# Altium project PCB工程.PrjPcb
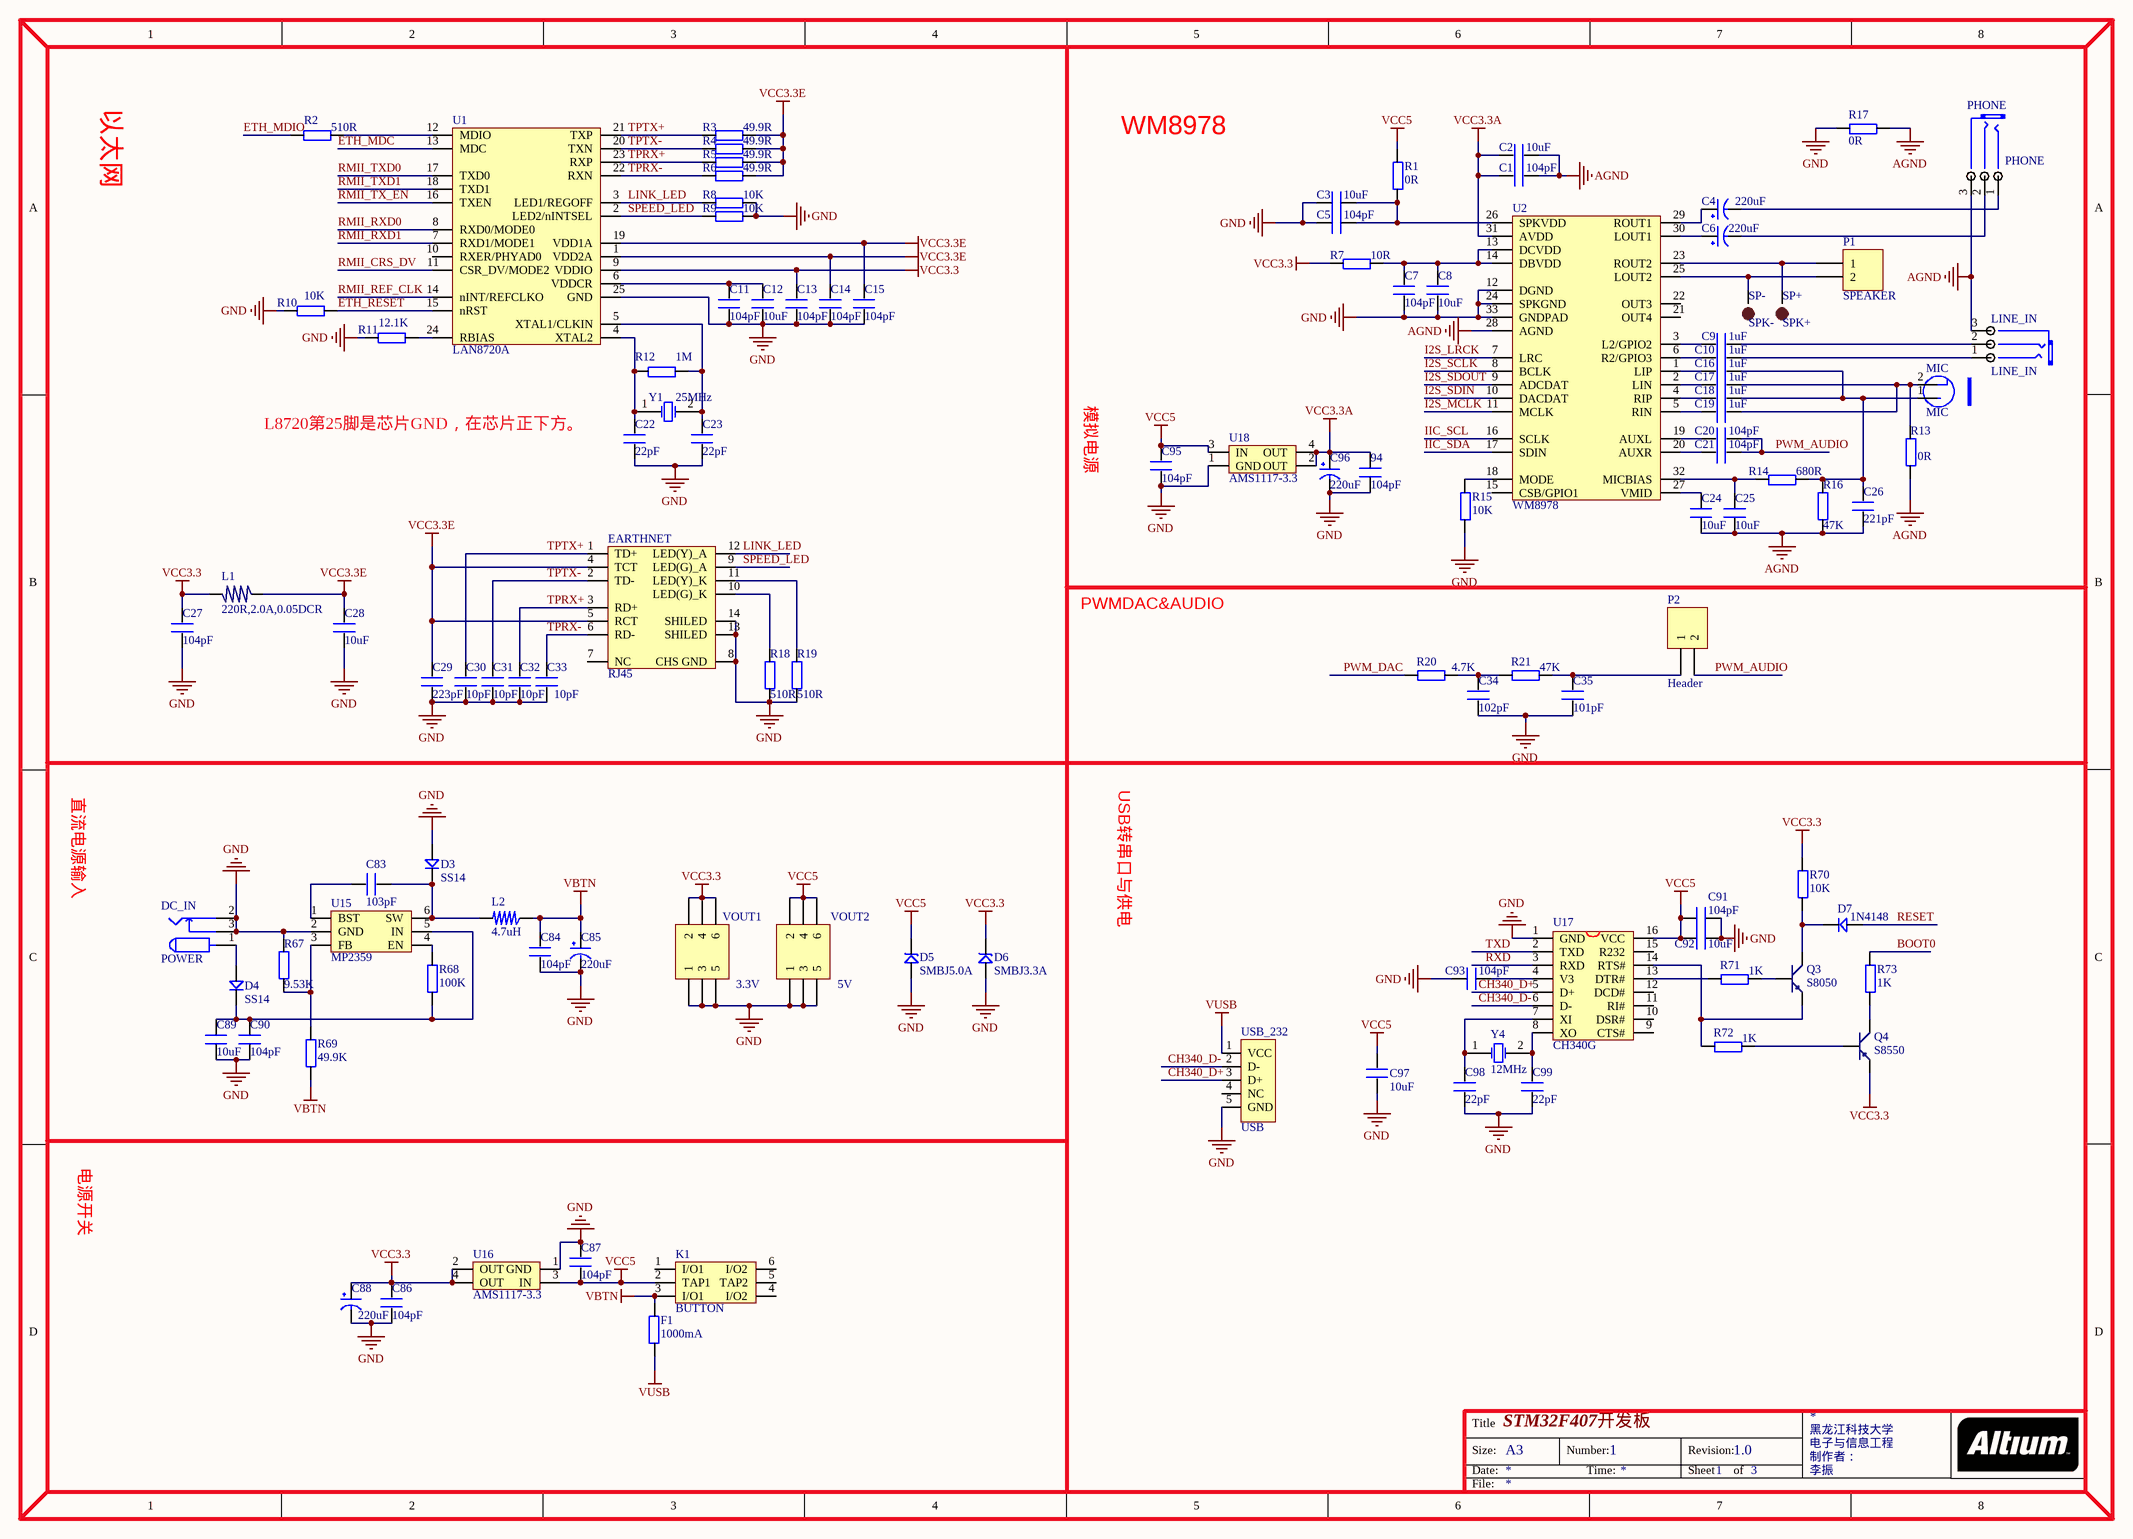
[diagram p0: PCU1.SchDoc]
3 sheets, 252 parts. Net scope: global (net labels, ports and power ports of the same name join across sheets).
Board file: PCB.PcbDoc
Sheets:
  PCU1.SchDoc
  CPU2.SchDoc
  CPU3.SchDoc

## Sheet PCU1.SchDoc: STM32F407开发板
size A3; DrawnBy: 李振; Address1: 黑龙江科技大学; Address2: 电子与信息工程; Address3: 制作者：; Address4: 李振; DocumentNumber: 1; Revision: 1.0; SheetNumber: 1; SheetTotal: 3

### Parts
94  104pF  [0603P]
C1  104pF  [0603P]
C2  10uF  [0603P]
C3  10uF  [0603P]
C4  220uF  [CC6.56.5]
C5  104pF  [0603P]
C6  220uF  [CC6.56.5]
C7  104pF  [0603P]
C8  10uF  [0603P]
C9  1uF  [0603P]
C10  1uF  [0603P]
C11  104pF  [0603P]
C12  10uF  [0603P]
C13  104pF  [0603P]
C14  104pF  [0603P]
C15  104pF  [0603P]
C16  1uF  [0603P]
C17  1uF  [0603P]
C18  1uF  [0603P]
C19  1uF  [0603P]
C20  104pF  [0603P]
C21  104pF  [0603P]
C22  22pF  [0603P]
C23  22pF  [0603P]
C24  10uF  [0603P]
C25  10uF  [0603P]
C26  221pF  [0603P]
C27  104pF  [0603P]
C28  10uF  [0603P]
C29  223pF  [0603P]
C30  10pF  [0603P]
C31  10pF  [0603P]
C32  10pF  [0603P]
C33  10pF  [0603P]
C34  102pF  [0603P]
C35  101pF  [0603P]
C83  103pF  [0603P]
C84  104pF  [0603P]
C85  220uF  [CC6.56.5]
C86  104pF  [0603P]
C87  104pF  [0603P]
C88  220uF  [CC6.56.5]
C89  10uF  [0603P]
C90  104pF  [0603P]
C91  104pF  [0603P]
C92  10uF  [0603P]
C93  104pF  [0603P]
C95  104pF  [0603P]
C96  220uF  [CC6.56.5]
C97  10uF  [0603P]
C98  22pF  [0603P]
C99  22pF  [0603P]
D3  SS14  [DIODE_SOP]
D4  SS14  [DIODE_SOP]
D5  SMBJ5.0A  [SMBJ]
D6  SMBJ3.3A  [SMBJ]
D7  1N4148  [DIODE_SOP]
DC_IN  POWER  [DC10B]
EARTHNET  RJ45  [HR911105A]
F1  1000mA  [0805]
K1  BUTTON  [BTN8.5*8.5]
L1  220R,2.0A,0.05DCR  [0603P]
L2  4.7uH  [L_SOP74]
LINE_IN  LINE_IN  [PHONE_ST]
MIC  MIC  [MIC]
P1  SPEAKER  [HDR1X2]
P2  Header  [HDR1X2]
PHONE  PHONE  [PHONE_ST]
Q3  S8050  [SOT-23R]
Q4  S8550  [SOT-23R]
R1  0R  [0603P]
R2  510R  [0603P]
R3  49.9R  [0603P]
R4  49.9R  [0603P]
R5  49.9R  [0603P]
R6  49.9R  [0603P]
R7  10R  [0603P]
R8  10K  [0603P]
R9  10K  [0603P]
R10  10K  [0603P]
R11  12.1K  [0603P]
R12  1M  [0603P]
R13  0R  [0603P]
R14  680R  [0603P]
R15  10K  [0603P]
R16  47K  [0603P]
R17  0R  [0603P]
R18  510R  [0603P]
R19  510R  [0603P]
R20  4.7K  [0603P]
R21  47K  [0603P]
R67  9.53K  [0603P]
R68  100K  [0603P]
R69  49.9K  [0603P]
R70  10K  [0603P]
R71  1K  [0603P]
R72  1K  [0603P]
R73  1K  [0603P]
SP+  SPK+  [TP-1.5]
SP-  SPK-  [TP-1.5]
U1  LAN8720A  [QFN24]
U2  WM8978  [qfn32]
U15  MP2359  [SOT-23-6]
U16  AMS1117-3.3  [AMS1117]
U17  CH340G  [SOP16M]
U18  AMS1117-3.3  [AMS1117]
USB_232  USB  [USB/SM0.8-6H5]
VOUT1  3.3V  [HDR2X3]
VOUT2  5V  [HDR2X3]
Y1  25MHz  [XTAL_US]
Y4  12MHz  [XTAL_US]

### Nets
AGND: C1.1 C2.1 C24.1 C25.1 C26.1 LINE_IN.3(COM) PHONE.3(COM) R13.1 R16.1 R17.2 U2.28(AGND)
GND: 94.1 C3.1 C5.1 C7.1 C8.1 C11.1 C12.1 C13.1 C14.1 C15.1 C22.1 C23.1 C27.1 C28.1 C29.1 C30.1 C31.1 C32.1 C33.1 C34.1 C35.1 C84.1 C85.2(GND) C86.1 C87.2 C88.2(GND) C89.1 C90.1 C91.1 C92.1 C93.1 C95.1 C96.2(GND) C97.1 C98.1 C99.1 D3.1 D5.1 D6.1 DC_IN.2 DC_IN.3 EARTHNET.8(CHS_GND) EARTHNET.13(SHILED) EARTHNET.14(SHILED) R8.2 R9.2 R10.1 R11.1 R15.1 R17.1 R18.1 R19.1 R67.2 U1.25(GND) U2.12(DGND) U2.24(SPKGND) U2.33(GNDPAD) U15.2(GND) U16.1(GND) U17.1(GND) U18.1(GND) USB_232.5(GND) VOUT1.1 VOUT1.3 VOUT1.5 VOUT2.1 VOUT2.3 VOUT2.5
VBTN: C84.2 C85.1(VCC) F1.1 K1.3(I/O1) L2.1 R69.1
VCC3.3: C13.2 C27.2 C86.2 C88.1(VCC) D6.2 L1.2 Q4.1(E) R7.1 R70.2 U1.9(VDDIO) U16.2(OUT) U16.4(OUT) VOUT1.2 VOUT1.4 VOUT1.6
VCC3.3A: 94.2 C1.2 C2.2 C96.1(VCC) U2.31(AVDD) U18.2(OUT) U18.4(OUT)
VCC3.3E: C14.2 C15.2 C28.2 C29.2 EARTHNET.4(TCT) EARTHNET.5(RCT) L1.1 R3.2 R4.2 R5.2 R6.2 U1.1(VDD2A) U1.19(VDD1A)
VCC5: C87.1 C91.2 C92.2 C95.2 C97.2 D5.2 K1.2(TAP1) R1.2 U16.3(IN) U17.16(VCC) U18.3(IN) VOUT2.2 VOUT2.4 VOUT2.6
VUSB: F1.2 USB_232.1(VCC)
BOOT0: R73.2
CH340_D+: U17.5(D+) USB_232.3(D+)
CH340_D-: U17.6(D-) USB_232.2(D-)
ETH_MDC: U1.13(MDC)
ETH_MDIO: R2.1
ETH_RESET: R10.2 U1.15(nRST)
I2S_LRCK: U2.7(LRC)
I2S_MCLK: U2.11(MCLK)  [project net DCMI_D0]
I2S_SCLK: U2.8(BCLK)
I2S_SDIN: U2.10(DACDAT)
I2S_SDOUT: U2.9(ADCDAT)
IIC_SCL: U2.16(SCLK)
IIC_SDA: U2.17(SDIN)
LINK_LED: EARTHNET.12(LED(Y)_A) R8.1 U1.3(LED1/REGOFF)
PWM_AUDIO: C20.2 C21.2 P2.2
PWM_DAC: R20.1  [project net PA3]
RESET: D7.1
RMII_CRS_DV: U1.11(CSR_DV/MODE2)  [project net PA7]
RMII_REF_CLK: U1.14(nINT/REFCLKO)  [project net PA1]
RMII_RXD0: U1.8(RXD0/MODE0)  [project net PC4]
RMII_RXD1: U1.7(RXD1/MODE1)  [project net PC5]
RMII_TX_EN: U1.16(TXEN)  [project net PG11]
RMII_TXD0: U1.17(TXD0)  [project net PG13]
RMII_TXD1: U1.18(TXD1)  [project net PG14]
RXD: U17.3(RXD)
SPEED_LED: EARTHNET.9(LED(G)_A) R9.1 U1.2(LED2/nINTSEL)
TPRX+: C32.2 EARTHNET.3(RD+) R5.1 U1.23(RXP)
TPRX-: C33.2 EARTHNET.6(RD-) R6.1 U1.22(RXN)
TPTX+: C30.2 EARTHNET.1(TD+) R3.1 U1.21(TXP)
TPTX-: C31.2 EARTHNET.2(TD-) R4.1 U1.20(TXN)
TXD: U17.2(TXD)
NetC3_2: C3.2 C5.2 R1.1 U2.26(SPKVDD)
NetC4_1: C4.1(VCC) U2.29(ROUT1)
NetC4_2: C4.2(GND) PHONE.1(CHL)
NetC6_1: C6.1(VCC) U2.30(LOUT1)
NetC6_2: C6.2(GND) PHONE.2(CHR)
NetC7_2: C7.2 C8.2 R7.2 U2.13(DCVDD) U2.14(DBVDD)
NetC9_1: C9.1 U2.3(L2/GPIO2)
NetC9_2: C9.2 LINE_IN.2(CHR)
NetC10_1: C10.1 U2.6(R2/GPIO3)
NetC10_2: C10.2 LINE_IN.1(CHL)
NetC11_2: C11.2 C12.2 U1.6(VDDCR)
NetC16_1: C16.1 U2.1(LIP)
NetC16_2: C16.2 C18.2 C26.2 MIC.1(VCC) R14.2 R16.2
NetC17_1: C17.1 U2.2(LIN)
NetC17_2: C17.2 C19.2 MIC.2(GND) R13.2
NetC18_1: C18.1 U2.4(RIP)
NetC19_1: C19.1 U2.5(RIN)
NetC20_1: C20.1 U2.19(AUXL)
NetC21_1: C21.1 U2.20(AUXR)
NetC22_2: C22.2 R12.1 U1.4(XTAL2) Y1.1(OSC1)
NetC23_2: C23.2 R12.2 U1.5(XTAL1/CLKIN) Y1.2(OSC2)
NetC24_2: C24.2 U2.27(VMID)
NetC25_2: C25.2 R14.1 U2.32(MICBIAS)
NetC34_2: C34.2 R20.2 R21.1
NetC35_2: C35.2 P2.1 R21.2
NetC83_1: C83.1 U15.1(BST)
NetC83_2: C83.2 D3.2 L2.2 U15.6(SW)
NetC89_2: C89.2 C90.2 D4.2 R68.1 U15.5(IN)
NetC93_2: C93.2 U17.4(V3)
NetC98_2: C98.2 U17.7(XI) Y4.1(OSC1)
NetC99_2: C99.2 U17.8(XO) Y4.2(OSC2)
NetD4_1: D4.1 DC_IN.1
NetD7_2: D7.2 Q3.3(C) R70.1
NetEARTHNET_10: EARTHNET.10(LED(G)_K) R18.2
NetEARTHNET_11: EARTHNET.11(LED(Y)_K) R19.2
NetP1_1: P1.1 SP+.1 U2.23(ROUT2)
NetP1_2: P1.2 SP-.1 U2.25(LOUT2)
NetQ3_1: Q3.1(E) R72.1 U17.14(RTS#)
NetQ3_2: Q3.2(B) R71.2
NetQ4_2: Q4.2(B) R72.2
NetQ4_3: Q4.3(C) R73.1
NetR2_2: R2.2 U1.12(MDIO)
NetR11_2: R11.2 U1.24(RBIAS)
NetR15_2: R15.2 U2.18(MODE)
NetR67_1: R67.1 R69.2 U15.3(FB)
NetR68_2: R68.2 U15.4(EN)
NetR71_1: R71.1 U17.13(DTR#)

Not connected (* = marked no-connect by the designer): EARTHNET 7(NC); K1 1(I/O1) 4(I/O2) 5(TAP2) 6(I/O2); U1 10(RXER/PHYAD0); U2 15(CSB/GPIO1) 21(OUT4) 22(OUT3); U17 9(CTS#) 10(DSR#) 11(RI#) 12(DCD#) 15(R232); USB_232 4(NC)

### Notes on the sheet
- 以太网
- WM8978
- L8720第25脚是芯片GND，在芯片正下方。
- 模拟电源
- PWMDAC&AUDIO
- 直流电源输入
- USB转串口与供电
- 电源开关

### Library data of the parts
94 C1-C3 C5 C7-C35 C83 C84 C86 C87 C89-C93 C95 C97-C99 = C
C4 C6 C85 C88 C96 = CAP
D3 D4 D7 = D
D5 D6 = SMBJ: TVS
DC_IN = POW
EARTHNET = HR911105
F1 R1-R21 R67-R73 = R
L1 = L
L2 = L_SOP
LINE_IN PHONE = PHONE_M
P1 = Header 2_1: Header, 2-Pin
P2 = Header 2: Header, 2-Pin
Q3 = NPN: 8050/BCW846/BCW847
Q4 = PNP: 8550/BCW68
SP+ SP- = TEST-POINT: 测试点
U1 = LAN8720: ETH PHY
U2 = WM8978: 24bit ADC&DAC
U15 = MP2359: DC DC Step Down IC
U16 U18 = AMS1117
U17 = CH340G: USB2UART
USB_232 = USB5
VOUT1 VOUT2 = Header 3X2: Header, 3-Pin, Dual row
Y1 Y4 = XTAL: Crystal Oscillator

## Sheet CPU2.SchDoc: STM32F407开发板
size A3; DrawnBy: 李振; Address1: 黑龙江科技大学; Address2: 电子与信息工程; Address3: 制作者：; Address4: 李振; DocumentNumber: 2; Revision: 1.0; SheetNumber: 2; SheetTotal: 3
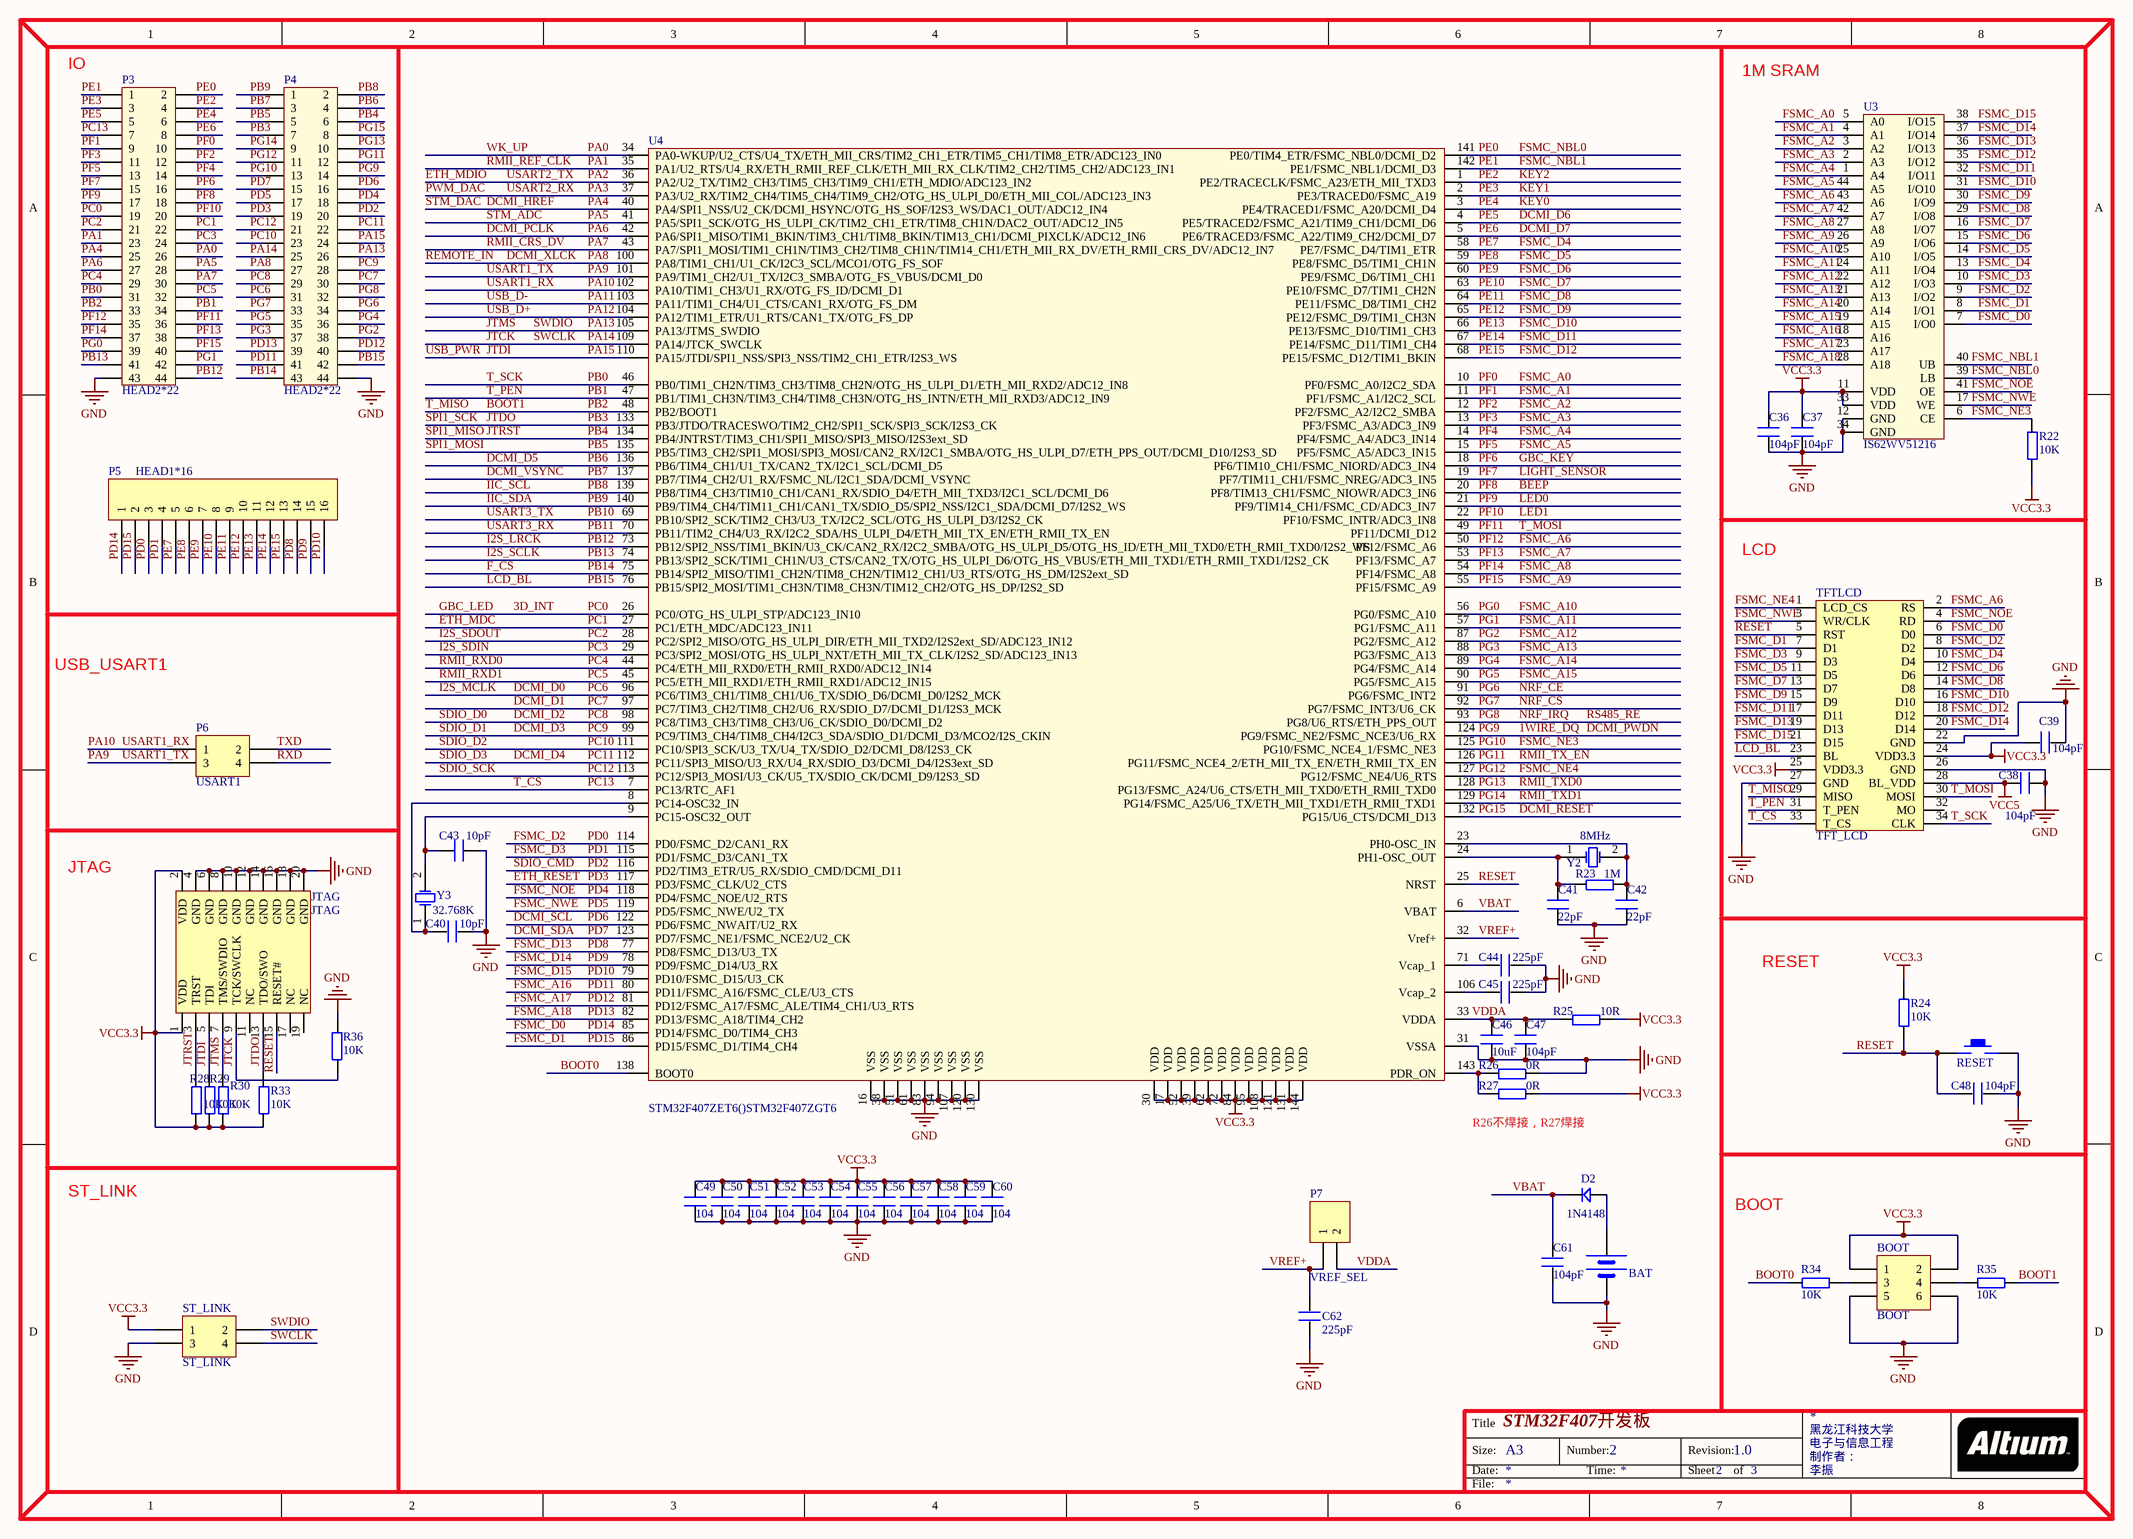
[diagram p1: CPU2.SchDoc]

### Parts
BAT  BATT  [BATM]  (value not drawn)
BOOT  BOOT  [HDR2X3]
C36  104pF  [0603P]
C37  104pF  [0603P]
C38  104pF  [0603P]
C39  104pF  [0603P]
C40  10pF  [0603P]
C41  22pF  [0603P]
C42  22pF  [0603P]
C43  10pF  [0603P]
C44  225pF  [0805]
C45  225pF  [0805]
C46  10uF  [0603P]
C47  104pF  [0603P]
C48  104pF  [0603P]
C49  104  [0603P]
C50  104  [0603P]
C51  104  [0603P]
C52  104  [0603P]
C53  104  [0603P]
C54  104  [0603P]
C55  104  [0603P]
C56  104  [0603P]
C57  104  [0603P]
C58  104  [0603P]
C59  104  [0603P]
C60  104  [0603P]
C61  104pF  [0603P]
C62  225pF  [0805]
D2  1N4148  [DIODE_SOP]
JTAG  JTAG  [JTAG_20]
P3  HEAD2*22  [HEAD2*22]
P4  HEAD2*22  [HEAD2*22]
P5  HEAD1*16  [HDR1X16]
P6  USART1  [HDR2X2]
P7  VREF_SEL  [HDR1X2]
R22  10K  [0603P]
R23  1M  [0603P]
R24  10K  [0603P]
R25  10R  [0603P]
R26  0R  [0603P]
R27  0R  [0603P]
R28  10K  [0603P]
R29  10K  [0603P]
R30  10K  [0603P]
R33  10K  [0603P]
R34  10K  [0603P]
R35  10K  [0603P]
R36  10K  [0603P]
RESET  KEY_M  [KEY_M]  (value not drawn)
ST_LINK  ST_LINK  [HDR2X2]
TFTLCD  TFT_LCD  [db2*17-4.3]
U3  IS62WV51216  [TSOP44]
U4  STM32F407ZET6()STM32F407ZGT6  [LQFP144]
Y2  8MHz  [XTAL_US]
Y3  32.768K  [XTAL32]

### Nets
GND: BAT.2(GND) BOOT.5 BOOT.6 C36.1 C37.1 C38.2 C39.2 C40.2 C41.1 C42.1 C43.2 C44.2 C45.2 C46.1 C47.1 C48.1 C49.1 C50.1 C51.1 C52.1 C53.1 C54.1 C55.1 C56.1 C57.1 C58.1 C59.1 C60.1 C61.1 C62.1 JTAG.4(GND) JTAG.6(GND) JTAG.8(GND) JTAG.10(GND) JTAG.12(GND) JTAG.14(GND) JTAG.16(GND) JTAG.18(GND) JTAG.20(GND) P3.43 P4.44 R26.2 R36.1 RESET.2 ST_LINK.3 TFTLCD.22(GND) TFTLCD.26(GND) TFTLCD.27(GND) U3.12(GND) U3.34(GND) U4.16(VSS) U4.31(VSSA) U4.38(VSS) U4.51(VSS) U4.61(VSS) U4.83(VSS) U4.94(VSS) U4.107(VSS) U4.120(VSS) U4.130(VSS)
VCC3.3: BOOT.1 BOOT.2 C36.2 C37.2 C39.1 C49.2 C50.2 C51.2 C52.2 C53.2 C54.2 C55.2 C56.2 C57.2 C58.2 C59.2 C60.2 JTAG.1(VDD) JTAG.2(VDD) R22.1 R24.2 R25.2 R27.2 R28.1 R29.1 R30.1 R33.1 ST_LINK.1 TFTLCD.24(VDD3.3) TFTLCD.25(VDD3.3) U3.11(VDD) U3.33(VDD) U4.17(VDD) U4.30(VDD) U4.39(VDD) U4.52(VDD) U4.62(VDD) U4.72(VDD) U4.84(VDD) U4.95(VDD) U4.108(VDD) U4.121(VDD) U4.131(VDD) U4.144(VDD)
VCC5: C38.1 TFTLCD.28(BL_VDD)
1WIRE_DQ: P4.14 U4.124(PG9/FSMC_NE2/FSMC_NCE3/U6_RX)  [also labelled DCMI_PWDN, PG9]
3D_INT: P3.19 U4.26(PC0/OTG_HS_ULPI_STP/ADC123_IN10)  [also labelled GBC_LED, PC0]
BEEP: P3.18 U4.20(PF8/TIM13_CH1/FSMC_NIOWR/ADC3_IN6)  [also labelled PF8]
BOOT0: R34.1 U4.138(BOOT0)
BOOT1: P3.33 R35.2 TFTLCD.29(MISO) U4.48(PB2/BOOT1)  [also labelled PB2, T_MISO]
DCMI_D0: P4.31 U4.96(PC6/TIM3_CH1/TIM8_CH1/U6_TX/SDIO_D6/DCMI_D0/I2S2_MCK)  [also labelled I2S_MCLK, PC6]
DCMI_D1: P4.30 U4.97(PC7/TIM3_CH2/TIM8_CH2/U6_RX/SDIO_D7/DCMI_D1/I2S3_MCK)  [also labelled PC7]
DCMI_D2: P4.29 U4.98(PC8/TIM3_CH3/TIM8_CH3/U6_CK/SDIO_D0/DCMI_D2)  [also labelled PC8, SDIO_D0]
DCMI_D3: P4.28 U4.99(PC9/TIM3_CH4/TIM8_CH4/I2C3_SDA/SDIO_D1/DCMI_D3/MCO2/I2S_CKIN)  [also labelled PC9, SDIO_D1]
DCMI_D4: P4.22 U4.112(PC11/SPI3_MISO/U3_RX/U4_RX/SDIO_D3/DCMI_D4/I2S3ext_SD)  [also labelled PC11, SDIO_D3]
DCMI_D5: P4.4 U4.136(PB6/TIM4_CH1/U1_TX/CAN2_TX/I2C1_SCL/DCMI_D5)  [also labelled PB6]
DCMI_D6: P3.5 U4.4(PE5/TRACED2/FSMC_A21/TIM9_CH1/DCMI_D6)  [also labelled PE5]
DCMI_D7: P3.8 U4.5(PE6/TRACED3/FSMC_A22/TIM9_CH2/DCMI_D7)  [also labelled PE6]
DCMI_HREF: P3.25 U4.40(PA4/SPI1_NSS/U2_CK/DCMI_HSYNC/OTG_HS_SOF/I2S3_WS/DAC1_OUT/ADC12_IN4)  [also labelled PA4, STM_DAC]
DCMI_PCLK: P3.27 U4.42(PA6/SPI1_MISO/TIM1_BKIN/TIM3_CH1/TIM8_BKIN/TIM13_CH1/DCMI_PIXCLK/ADC12_IN6)  [also labelled PA6]
DCMI_RESET: P4.8 U4.132(PG15/U6_CTS/DCMI_D13)  [also labelled PG15]
DCMI_SCL: P4.16 U4.122(PD6/FSMC_NWAIT/U2_RX)  [also labelled PD6]
DCMI_SDA: P4.15 U4.123(PD7/FSMC_NE1/FSMC_NCE2/U2_CK)  [also labelled PD7]
DCMI_VSYNC: P4.3 U4.137(PB7/TIM4_CH2/U1_RX/FSMC_NL/I2C1_SDA/DCMI_VSYNC)  [also labelled PB7]
DCMI_XLCK: P4.27 U4.100(PA8/TIM1_CH1/U1_CK/I2C3_SCL/MCO1/OTG_FS_SOF)  [also labelled PA8, REMOTE_IN]
ETH_MDC: P3.22 U4.27(PC1/ETH_MDC/ADC123_IN11)  [also labelled PC1]
ETH_MDIO: U4.36(PA2/U2_TX/TIM2_CH3/TIM5_CH3/TIM9_CH1/ETH_MDIO/ADC123_IN2)  [also labelled PA2, USART2_TX]
ETH_RESET: P4.19 U4.117(PD3/FSMC_CLK/U2_CTS)  [also labelled PD3]
F_CS: P4.43 U4.75(PB14/SPI2_MISO/TIM1_CH2N/TIM8_CH2N/TIM12_CH1/U3_RTS/OTG_HS_DM/I2S2ext_SD)  [also labelled PB14]
FSMC_A0: P3.10 U3.5(A0) U4.10(PF0/FSMC_A0/I2C2_SDA)  [also labelled PF0]
FSMC_A1: P3.9 U3.4(A1) U4.11(PF1/FSMC_A1/I2C2_SCL)  [also labelled PF1]
FSMC_A2: P3.12 U3.3(A2) U4.12(PF2/FSMC_A2/I2C2_SMBA)  [also labelled PF2]
FSMC_A3: P3.11 U3.2(A3) U4.13(PF3/FSMC_A3/ADC3_IN9)  [also labelled PF3]
FSMC_A4: P3.14 U3.1(A4) U4.14(PF4/FSMC_A4/ADC3_IN14)  [also labelled PF4]
FSMC_A5: P3.13 U3.44(A5) U4.15(PF5/FSMC_A5/ADC3_IN15)  [also labelled PF5]
FSMC_A6: P3.35 TFTLCD.2(RS) U3.43(A6) U4.50(PF12/FSMC_A6)  [also labelled PF12]
FSMC_A7: P3.38 U3.42(A7) U4.53(PF13/FSMC_A7)  [also labelled PF13]
FSMC_A8: P3.37 U3.27(A8) U4.54(PF14/FSMC_A8)  [also labelled PF14]
FSMC_A9: P3.40 U3.26(A9) U4.55(PF15/FSMC_A9)  [also labelled PF15]
FSMC_A10: P3.39 U3.25(A10) U4.56(PG0/FSMC_A10)  [also labelled PG0]
FSMC_A11: P3.42 U3.24(A11) U4.57(PG1/FSMC_A11)  [also labelled PG1]
FSMC_A12: P4.38 U3.22(A12) U4.87(PG2/FSMC_A12)  [also labelled PG2]
FSMC_A13: P4.37 U3.21(A13) U4.88(PG3/FSMC_A13)  [also labelled PG3]
FSMC_A14: P4.36 U3.20(A14) U4.89(PG4/FSMC_A14)  [also labelled PG4]
FSMC_A15: P4.35 U3.19(A15) U4.90(PG5/FSMC_A15)  [also labelled PG5]
FSMC_A16: P4.41 U3.18(A16) U4.80(PD11/FSMC_A16/FSMC_CLE/U3_CTS)  [also labelled PD11]
FSMC_A17: P4.40 U3.23(A17) U4.81(PD12/FSMC_A17/FSMC_ALE/TIM4_CH1/U3_RTS)  [also labelled PD12]
FSMC_A18: P4.39 U3.28(A18) U4.82(PD13/FSMC_A18/TIM4_CH2)  [also labelled PD13]
FSMC_D0: P5.1 TFTLCD.6(D0) U3.7(I/O0) U4.85(PD14/FSMC_D0/TIM4_CH3)  [also labelled PD14]
FSMC_D1: P5.2 TFTLCD.7(D1) U3.8(I/O1) U4.86(PD15/FSMC_D1/TIM4_CH4)  [also labelled PD15]
FSMC_D2: P5.3 TFTLCD.8(D2) U3.9(I/O2) U4.114(PD0/FSMC_D2/CAN1_RX)  [also labelled PD0]
FSMC_D3: P5.4 TFTLCD.9(D3) U3.10(I/O3) U4.115(PD1/FSMC_D3/CAN1_TX)  [also labelled PD1]
FSMC_D4: P5.5 TFTLCD.10(D4) U3.13(I/O4) U4.58(PE7/FSMC_D4/TIM1_ETR)  [also labelled PE7]
FSMC_D5: P5.6 TFTLCD.11(D5) U3.14(I/O5) U4.59(PE8/FSMC_D5/TIM1_CH1N)  [also labelled PE8]
FSMC_D6: P5.7 TFTLCD.12(D6) U3.15(I/O6) U4.60(PE9/FSMC_D6/TIM1_CH1)  [also labelled PE9]
FSMC_D7: P5.8 TFTLCD.13(D7) U3.16(I/O7) U4.63(PE10/FSMC_D7/TIM1_CH2N)  [also labelled PE10]
FSMC_D8: P5.9 TFTLCD.14(D8) U3.29(I/O8) U4.64(PE11/FSMC_D8/TIM1_CH2)  [also labelled PE11]
FSMC_D9: P5.10 TFTLCD.15(D9) U3.30(I/O9) U4.65(PE12/FSMC_D9/TIM1_CH3N)  [also labelled PE12]
FSMC_D10: P5.11 TFTLCD.16(D10) U3.31(I/O10) U4.66(PE13/FSMC_D10/TIM1_CH3)  [also labelled PE13]
FSMC_D11: P5.12 TFTLCD.17(D11) U3.32(I/O11) U4.67(PE14/FSMC_D11/TIM1_CH4)  [also labelled PE14]
FSMC_D12: P5.13 TFTLCD.18(D12) U3.35(I/O12) U4.68(PE15/FSMC_D12/TIM1_BKIN)  [also labelled PE15]
FSMC_D13: P5.14 TFTLCD.19(D13) U3.36(I/O13) U4.77(PD8/FSMC_D13/U3_TX)  [also labelled PD8]
FSMC_D14: P5.15 TFTLCD.20(D14) U3.37(I/O14) U4.78(PD9/FSMC_D14/U3_RX)  [also labelled PD9]
FSMC_D15: P5.16 TFTLCD.21(D15) U3.38(I/O15) U4.79(PD10/FSMC_D15/U3_CK)  [also labelled PD10]
FSMC_NBL0: P3.2 U3.39(LB) U4.141(PE0/TIM4_ETR/FSMC_NBL0/DCMI_D2)  [also labelled PE0]
FSMC_NBL1: P3.1 U3.40(UB) U4.142(PE1/FSMC_NBL1/DCMI_D3)  [also labelled PE1]
FSMC_NE3: P4.13 R22.2 U3.6(CE) U4.125(PG10/FSMC_NCE4_1/FSMC_NE3)  [also labelled PG10]
FSMC_NE4: P4.11 TFTLCD.1(LCD_CS) U4.127(PG12/FSMC_NE4/U6_RTS)  [also labelled PG12]
FSMC_NOE: P4.18 TFTLCD.4(RD) U3.41(OE) U4.118(PD4/FSMC_NOE/U2_RTS)  [also labelled PD4]
FSMC_NWE: P4.17 TFTLCD.3(WR/CLK) U3.17(WE) U4.119(PD5/FSMC_NWE/U2_TX)  [also labelled PD5]
GBC_KEY: P3.16 U4.18(PF6/TIM10_CH1/FSMC_NIORD/ADC3_IN4)  [also labelled PF6]
I2S_LRCK: P3.44 U4.73(PB12/SPI2_NSS/TIM1_BKIN/U3_CK/CAN2_RX/I2C2_SMBA/OTG_HS_ULPI_D5/OTG_HS_ID/ETH_MII_TXD0/ETH_RMII_TXD0/I2S2_WS)  [also labelled PB12]
I2S_SCLK: P3.41 U4.74(PB13/SPI2_SCK/TIM1_CH1N/U3_CTS/CAN2_TX/OTG_HS_ULPI_D6/OTG_HS_VBUS/ETH_MII_TXD1/ETH_RMII_TXD1/I2S2_CK)  [also labelled PB13]
I2S_SDIN: P3.24 U4.29(PC3/SPI2_MOSI/OTG_HS_ULPI_NXT/ETH_MII_TX_CLK/I2S2_SD/ADC123_IN13)  [also labelled PC3]
I2S_SDOUT: P3.21 U4.28(PC2/SPI2_MISO/OTG_HS_ULPI_DIR/ETH_MII_TXD2/I2S2ext_SD/ADC123_IN12)  [also labelled PC2]
IIC_SCL: P4.2 U4.139(PB8/TIM4_CH3/TIM10_CH1/CAN1_RX/SDIO_D4/ETH_MII_TXD3/I2C1_SCL/DCMI_D6)  [also labelled PB8]
IIC_SDA: P4.1 U4.140(PB9/TIM4_CH4/TIM11_CH1/CAN1_TX/SDIO_D5/SPI2_NSS/I2C1_SDA/DCMI_D7/I2S2_WS)  [also labelled PB9]
JTCK: JTAG.9(TCK/SWCLK) P4.25 R36.2 ST_LINK.4 U4.109(PA14/JTCK_SWCLK)  [also labelled PA14, SWCLK]
JTDI: JTAG.5(TDI) P4.24 R29.2 U4.110(PA15/JTDI/SPI1_NSS/SPI3_NSS/TIM2_CH1_ETR/I2S3_WS)  [also labelled PA15, USB_PWR]
JTDO: JTAG.13(TDO/SWO) P4.7 R33.2 U4.133(PB3/JTDO/TRACESWO/TIM2_CH2/SPI1_SCK/SPI3_SCK/I2S3_CK)  [also labelled PB3, SPI1_SCK]
JTMS: JTAG.7(TMS/SWDIO) P4.26 R30.2 ST_LINK.2 U4.105(PA13/JTMS_SWDIO)  [also labelled PA13, SWDIO]
JTRST: JTAG.3(TRST) P4.6 R28.2 U4.134(PB4/JNTRST/TIM3_CH1/SPI1_MISO/SPI3_MISO/I2S3ext_SD)  [also labelled PB4, SPI1_MISO]
KEY0: P3.6 U4.3(PE4/TRACED1/FSMC_A20/DCMI_D4)  [also labelled PE4]
KEY1: P3.3 U4.2(PE3/TRACED0/FSMC_A19)  [also labelled PE3]
KEY2: P3.4 U4.1(PE2/TRACECLK/FSMC_A23/ETH_MII_TXD3)  [also labelled PE2]
LCD_BL: P4.42 TFTLCD.23(BL) U4.76(PB15/SPI2_MOSI/TIM1_CH3N/TIM8_CH3N/TIM12_CH2/OTG_HS_DP/I2S2_SD)  [also labelled PB15]
LED0: P3.17 U4.21(PF9/TIM14_CH1/FSMC_CD/ADC3_IN7)  [also labelled PF9]
LED1: P3.20 U4.22(PF10/FSMC_INTR/ADC3_IN8)  [also labelled PF10]
LIGHT_SENSOR: P3.15 U4.19(PF7/TIM11_CH1/FSMC_NREG/ADC3_IN5)  [also labelled PF7]
NRF_CE: P4.34 U4.91(PG6/FSMC_INT2)  [also labelled PG6]
NRF_CS: P4.33 U4.92(PG7/FSMC_INT3/U6_CK)  [also labelled PG7]
NRF_IRQ: P4.32 U4.93(PG8/U6_RTS/ETH_PPS_OUT)  [also labelled PG8, RS485_RE]
PA0: P3.26 U4.34(PA0-WKUP/U2_CTS/U4_TX/ETH_MII_CRS/TIM2_CH1_ETR/TIM5_CH1/TIM8_ETR/ADC123_IN0)  [also labelled WK_UP]
PA1: P3.23 U4.35(PA1/U2_RTS/U4_RX/ETH_RMII_REF_CLK/ETH_MII_RX_CLK/TIM2_CH2/TIM5_CH2/ADC123_IN1)  [also labelled RMII_REF_CLK]
PA3: U4.37(PA3/U2_RX/TIM2_CH4/TIM5_CH4/TIM9_CH2/OTG_HS_ULPI_D0/ETH_MII_COL/ADC123_IN3)  [also labelled PWM_DAC, USART2_RX]
PA5: P3.28 U4.41(PA5/SPI1_SCK/OTG_HS_ULPI_CK/TIM2_CH1_ETR/TIM8_CH1N/DAC2_OUT/ADC12_IN5)  [also labelled STM_ADC]
PA7: P3.30 U4.43(PA7/SPI1_MOSI/TIM1_CH1N/TIM3_CH2/TIM8_CH1N/TIM14_CH1/ETH_MII_RX_DV/ETH_RMII_CRS_DV/ADC12_IN7)  [also labelled RMII_CRS_DV]
PA9: P6.3 U4.101(PA9/TIM1_CH2/U1_TX/I2C3_SMBA/OTG_FS_VBUS/DCMI_D0)  [also labelled USART1_TX]
PA10: P6.1 U4.102(PA10/TIM1_CH3/U1_RX/OTG_FS_ID/DCMI_D1)  [also labelled USART1_RX]
PA11: U4.103(PA11/TIM1_CH4/U1_CTS/CAN1_RX/OTG_FS_DM)  [also labelled USB_D-]
PA12: U4.104(PA12/TIM1_ETR/U1_RTS/CAN1_TX/OTG_FS_DP)  [also labelled USB_D+]
PB0: P3.31 TFTLCD.34(CLK) U4.46(PB0/TIM1_CH2N/TIM3_CH3/TIM8_CH2N/OTG_HS_ULPI_D1/ETH_MII_RXD2/ADC12_IN8)  [also labelled T_SCK]
PB1: P3.34 TFTLCD.31(T_PEN) U4.47(PB1/TIM1_CH3N/TIM3_CH4/TIM8_CH3N/OTG_HS_INTN/ETH_MII_RXD3/ADC12_IN9)  [also labelled T_PEN]
PB5: P4.5 U4.135(PB5/TIM3_CH2/SPI1_MOSI/SPI3_MOSI/CAN2_RX/I2C1_SMBA/OTG_HS_ULPI_D7/ETH_PPS_OUT/DCMI_D10/I2S3_SD)  [also labelled SPI1_MOSI]
PB10: U4.69(PB10/SPI2_SCK/TIM2_CH3/U3_TX/I2C2_SCL/OTG_HS_ULPI_D3/I2S2_CK)  [also labelled USART3_TX]
PB11: U4.70(PB11/TIM2_CH4/U3_RX/I2C2_SDA/HS_ULPI_D4/ETH_MII_TX_EN/ETH_RMII_TX_EN)  [also labelled USART3_RX]
PC4: P3.29 U4.44(PC4/ETH_MII_RXD0/ETH_RMII_RXD0/ADC12_IN14)  [also labelled RMII_RXD0]
PC5: P3.32 U4.45(PC5/ETH_MII_RXD1/ETH_RMII_RXD1/ADC12_IN15)  [also labelled RMII_RXD1]
PC10: P4.23 U4.111(PC10/SPI3_SCK/U3_TX/U4_TX/SDIO_D2/DCMI_D8/I2S3_CK)  [also labelled SDIO_D2]
PC12: P4.21 U4.113(PC12/SPI3_MOSI/U3_CK/U5_TX/SDIO_CK/DCMI_D9/I2S3_SD)  [also labelled SDIO_SCK]
PC13: P3.7 TFTLCD.33(T_CS) U4.7(PC13/RTC_AF1)  [also labelled T_CS]
PD2: P4.20 U4.116(PD2/TIM3_ETR/U5_RX/SDIO_CMD/DCMI_D11)  [also labelled SDIO_CMD]
PF11: P3.36 TFTLCD.30(MOSI) U4.49(PF11/DCMI_D12)  [also labelled T_MOSI]
PG11: P4.12 U4.126(PG11/FSMC_NCE4_2/ETH_MII_TX_EN/ETH_RMII_TX_EN)  [also labelled RMII_TX_EN]
PG13: P4.10 U4.128(PG13/FSMC_A24/U6_CTS/ETH_MII_TXD0/ETH_RMII_TXD0)  [also labelled RMII_TXD0]
PG14: P4.9 U4.129(PG14/FSMC_A25/U6_TX/ETH_MII_TXD1/ETH_RMII_TXD1)  [also labelled RMII_TXD1]
RESET: C48.2 JTAG.15(RESET#) R24.1 RESET.1 TFTLCD.5(RST) U4.25(NRST)
RXD: P6.4
TXD: P6.2
VBAT: C61.2 D2.2 U4.6(VBAT)
VDDA: C46.2 C47.2 P7.2 R25.1 U4.33(VDDA)
VREF+: C62.2 P7.1 U4.32(Vref+)
NetBAT_1: BAT.1(VCC) D2.1
NetBOOT_3: BOOT.3 R34.2
NetBOOT_4: BOOT.4 R35.1
NetC40_1: C40.1 U4.8(PC14-OSC32_IN) Y3.1(OSC1)
NetC41_2: C41.2 R23.1 U4.24(PH1-OSC_OUT) Y2.1(OSC1)
NetC42_2: C42.2 R23.2 U4.23(PH0-OSC_IN) Y2.2(OSC2)
NetC43_1: C43.1 U4.9(PC15-OSC32_OUT) Y3.2(OSC2)
NetC44_1: C44.1 U4.71(Vcap_1)
NetC45_1: C45.1 U4.106(Vcap_2)
NetR26_1: R26.1 R27.1 U4.143(PDR_ON)

Not connected (* = marked no-connect by the designer): JTAG 11(NC) 17(NC) 19(NC); TFTLCD 32(MO)

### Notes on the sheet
- (near P3) IO
- 1M SRAM
- LCD
- USB_USART1
- JTAG
- RESET
- (near R27) R26不焊接，R27焊接
- ST_LINK
- BOOT

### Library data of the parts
BAT = BAT
BOOT = Header 3X2: Header, 3-Pin, Dual row
C36-C62 = C
D2 = D
P5 = Header 16: Header, 16-Pin
P6 ST_LINK = Header 2X2: Header, 2-Pin, Dual row
P7 = Header 2: Header, 2-Pin
R22-R30 R33-R36 = R
U4 = STM32F407ZET6
Y2 = XTAL: Crystal Oscillator
Y3 = XTAL_1: Crystal Oscillator

## Sheet CPU3.SchDoc: STM32F407开发板
size A3; Author: 李振; DrawnBy: 李振; Address1: 黑龙江科技大学; Address2: 电子与信息工程; Address3: 制作者：; Address4: 李振; DocumentNumber: 3; Revision: 1.0; SheetNumber: 3; SheetTotal: 3
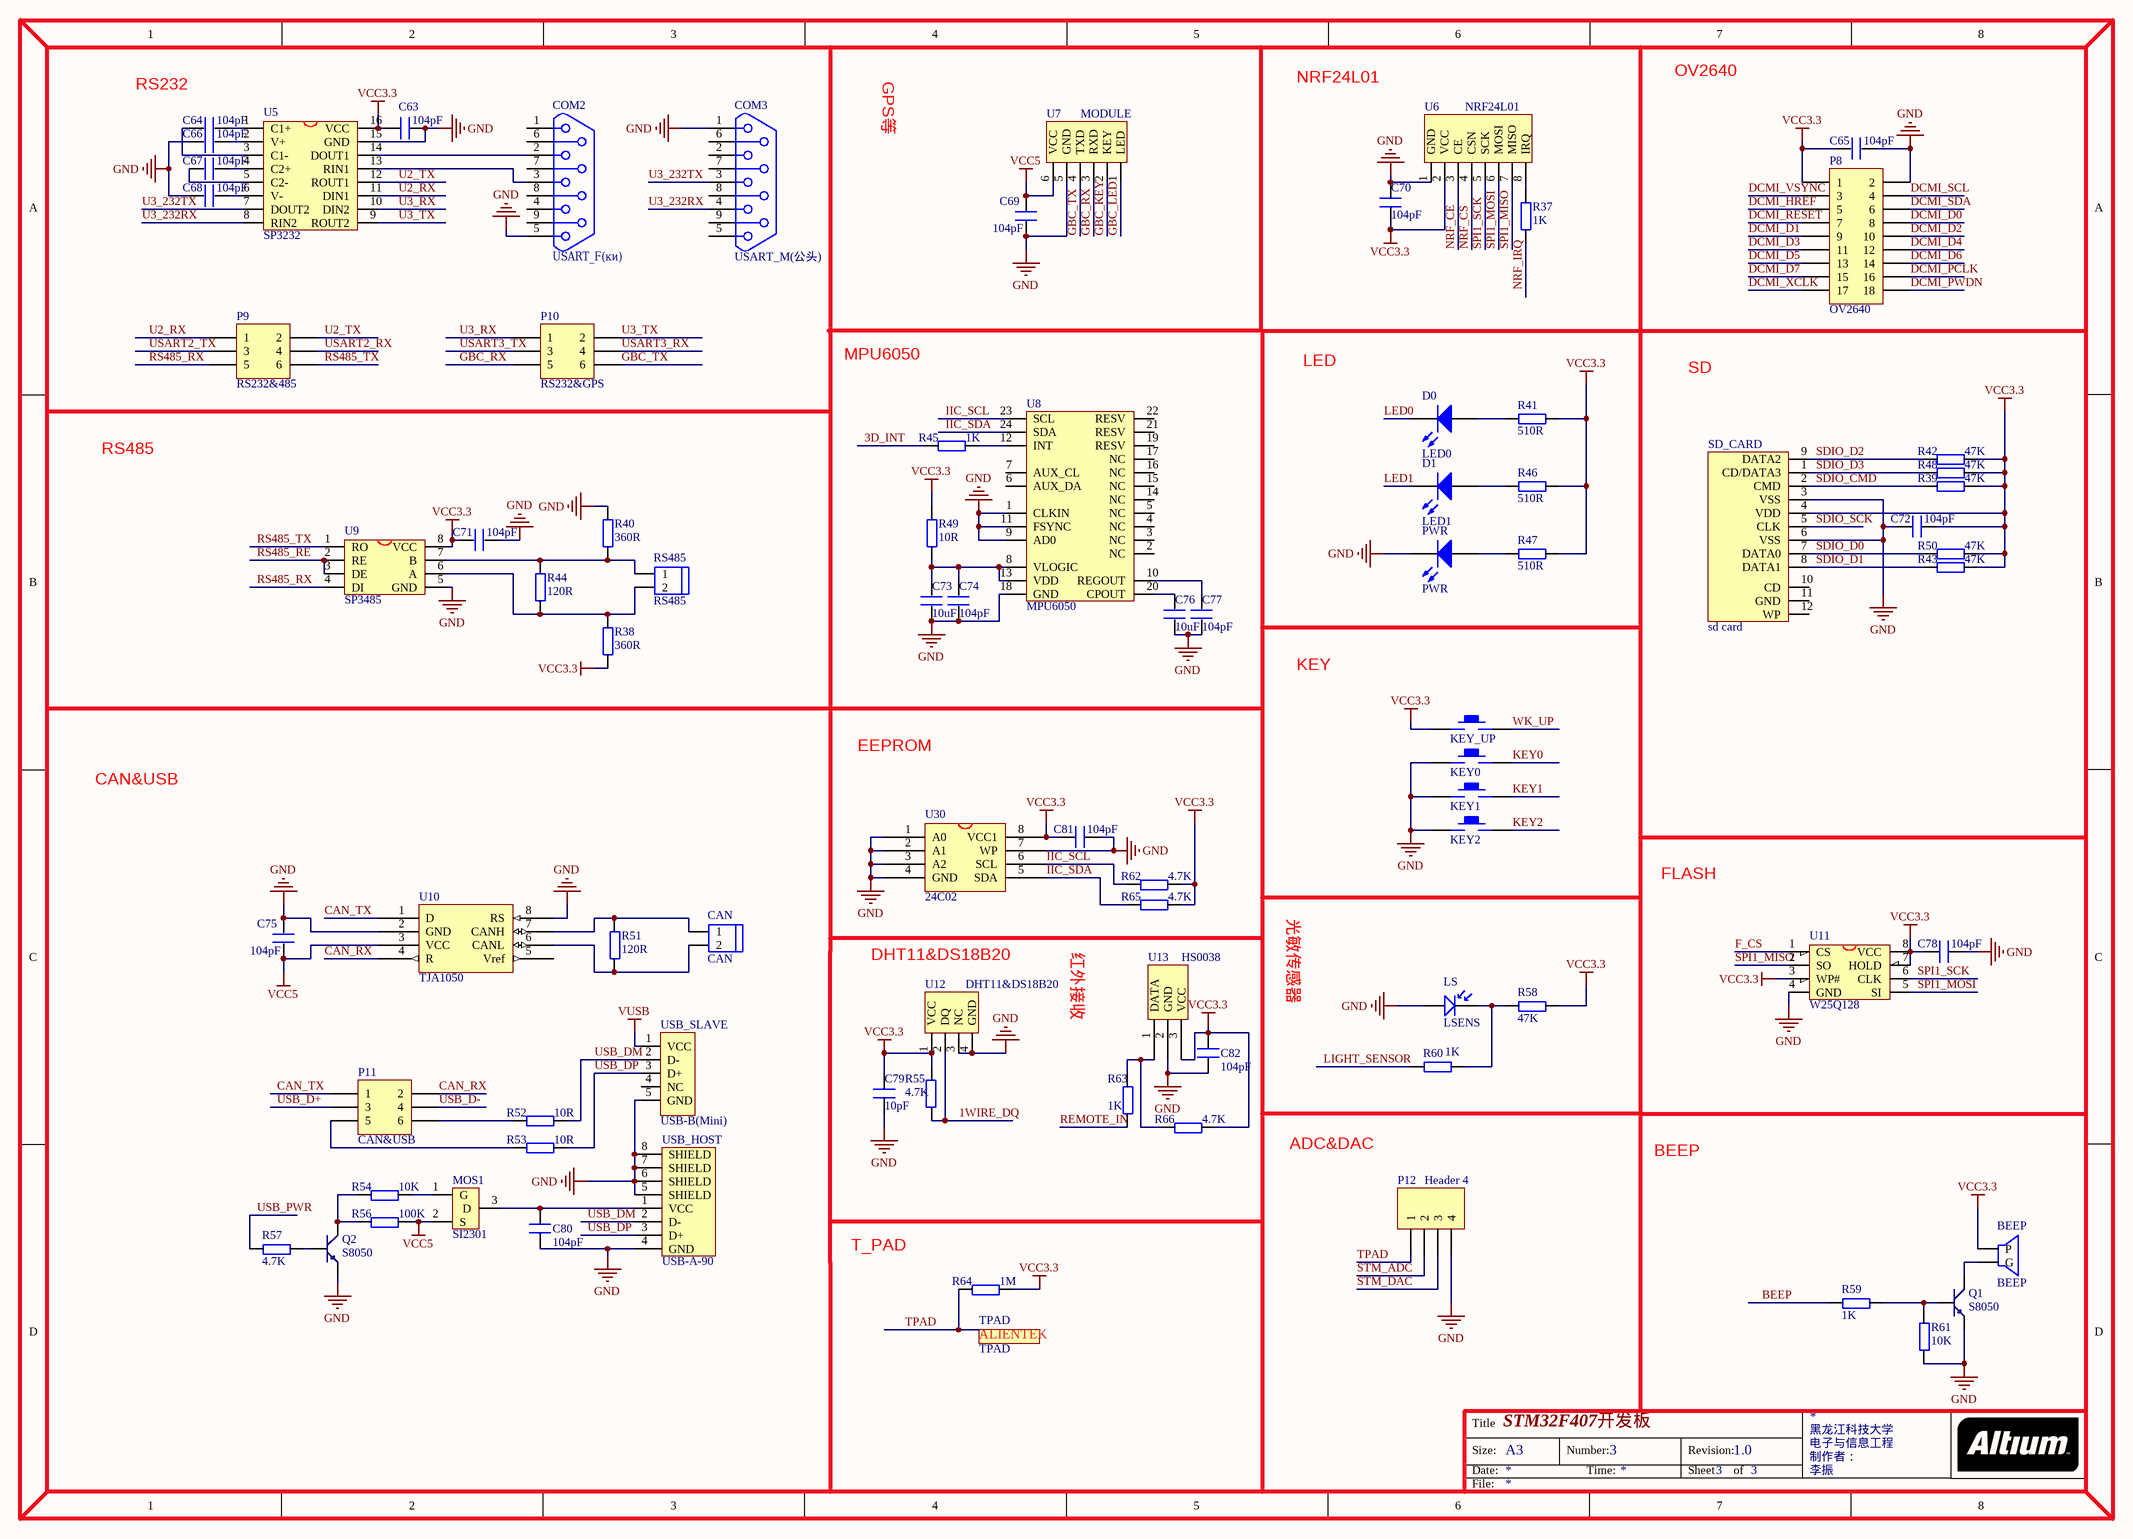
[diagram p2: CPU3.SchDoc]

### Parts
BEEP  BEEP  [BELL-5]
C63  104pF  [0603P]
C64  104pF  [0603P]
C65  104pF  [0603P]
C66  104pF  [0603P]
C67  104pF  [0603P]
C68  104pF  [0603P]
C69  104pF  [0603P]
C70  104pF  [0603P]
C71  104pF  [0603P]
C72  104pF  [0603P]
C73  10uF  [0603P]
C74  104pF  [0603P]
C75  104pF  [0603P]
C76  10uF  [0603P]
C77  104pF  [0603P]
C78  104pF  [0603P]
C79  10pF  [0603P]
C80  104pF  [0603P]
C81  104pF  [0603P]
C82  104pF  [0603P]
CAN  CAN  [HEAD2L-0.8]
COM2  USART_F(ĸͷ)  [DB9]
COM3  USART_M(公头)  [DB9]
D0  LED0  [SMDLED]
D1  LED1  [SMDLED]
KEY0  KEY0  [KEY_M]  (value not drawn)
KEY1  KEY0  [KEY_M]  (value not drawn)
KEY2  KEY0  [KEY_M]  (value not drawn)
KEY_UP  KEY_UP  [KEY_M]  (value not drawn)
LS  LSENS  [SMDLED]
MOS1  SI2301  [SO-G3/C2.5]
P8  OV2640  [HDR2X9]
P9  RS232&485  [HDR2X3]
P10  RS232&GPS  [HDR2X3]
P11  CAN&USB  [HDR2X3]
P12  Header 4  [HDR1X4]
PWR  PWR  [SMDLED]
Q1  S8050  [SOT-23R]
Q2  S8050  [SOT-23R]
R37  1K  [0603P]
R38  360R  [0603P]
R39  47K  [0603P]
R40  360R  [0603P]
R41  510R  [0603P]
R42  47K  [0603P]
R43  47K  [0603P]
R44  120R  [0603P]
R45  1K  [0603P]
R46  510R  [0603P]
R47  510R  [0603P]
R48  47K  [0603P]
R49  10R  [0603P]
R50  47K  [0603P]
R51  120R  [0603P]
R52  10R  [0603P]
R53  10R  [0603P]
R54  10K  [0603P]
R55  4.7K  [0603P]
R56  100K  [0603P]
R57  4.7K  [0603P]
R58  47K  [0603P]
R59  1K  [0603P]
R60  1K  [0603P]
R61  10K  [0603P]
R62  4.7K  [0603P]
R63  1K  [0603P]
R64  1M  [0603P]
R65  4.7K  [0603P]
R66  4.7K  [0603P]
RS485  RS485  [HEAD2L-0.8]
SD_CARD  sd card  [SDCARD_L]
TPAD  TPAD  [ALIENTEK_PAD]
U5  SP3232  [SOP16M]
U6  NRF24L01  [NRF24L01]
U7  MODULE  [HEAD6]
U8  MPU6050  [QFN24]
U9  SP3485  [SOP-8]
U10  TJA1050  [SOP-8]
U11  W25Q128  [SOIC-8]
U12  DHT11&DS18B20  [DHT11]
U13  HS0038  [HS0038]
U30  24C02  [SOP-8]
USB_HOST  USB-A-90  [USB-A-90]
USB_SLAVE  USB-B(Mini)  [USB/SM0.8-6H5]

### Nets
GND: C63.2 C65.2 C66.1 C68.1 C69.1 C70.2 C71.2 C72.1 C73.1 C74.1 C75.2 C76.1 C77.1 C78.2 C79.1 C80.1 C81.2 C82.1 COM2.5 COM3.1 KEY0.1 KEY1.1 KEY2.1 LS.1 P8.2 P12.4 PWR.2(K) Q1.1(E) Q2.1(E) R40.2 R61.1 SD_CARD.3(VSS) SD_CARD.6(VSS) U5.15(GND) U6.1(GND) U7.5(GND) U8.1(CLKIN) U8.9(AD0) U8.11(FSYNC) U8.18(GND) U9.5(GND) U10.2(GND) U10.8(RS) U11.4(GND) U12.3(NC) U12.4(GND) U13.2(GND) U30.1(A0) U30.2(A1) U30.3(A2) U30.4(GND) U30.7(WP) USB_HOST.4(GND) USB_HOST.5(SHIELD) USB_HOST.6(SHIELD) USB_HOST.7(SHIELD) USB_HOST.8(SHIELD) USB_SLAVE.5(GND)
VCC3.3: BEEP.1(P) C63.1 C65.1 C70.1 C71.1 C72.2 C78.1 C79.2 C81.1 C82.2 KEY_UP.1 P8.1 R38.1 R39.2 R41.2 R42.2 R43.2 R46.2 R47.2 R48.2 R49.2 R50.2 R55.1 R58.2 R62.2 R64.2 R65.2 R66.2 SD_CARD.4(VDD) U5.16(VCC) U6.2(VCC) U9.8(VCC) U11.3(WP#) U11.7(HOLD) U11.8(VCC) U12.1(VCC) U13.3(VCC) U30.8(VCC1)
VCC5: C69.2 C75.1 MOS1.2(S) R56.2 U7.6(VCC) U10.3(VCC)
VUSB: USB_SLAVE.1(VCC)
1WIRE_DQ: P8.18 R55.2 U12.2(DQ)  [also labelled DCMI_PWDN]
3D_INT: R45.1 U7.1(LED)  [also labelled GBC_LED]
BEEP: R59.1
CAN_RX: P11.2 U10.4(R)
CAN_TX: P11.1 U10.1(D)
DCMI_D0: P8.8
DCMI_D1: P8.9
DCMI_D2: P8.10 R50.1 SD_CARD.7(DATA0)  [also labelled SDIO_D0]
DCMI_D3: P8.11 R43.1 SD_CARD.8(DATA1)  [also labelled SDIO_D1]
DCMI_D4: P8.12 R48.1 SD_CARD.1(CD/DATA3)  [also labelled SDIO_D3]
DCMI_D5: P8.13
DCMI_D6: P8.14
DCMI_D7: P8.15
DCMI_HREF: P8.5 P12.3  [also labelled STM_DAC]
DCMI_PCLK: P8.16
DCMI_RESET: P8.7
DCMI_SCL: P8.4
DCMI_SDA: P8.6
DCMI_VSYNC: P8.3
DCMI_XCLK: P8.17
F_CS: U11.1(CS)
GBC_KEY: U7.2(KEY)
GBC_RX: P10.5 U7.3(RXD)
GBC_TX: P10.6 U7.4(TXD)
IIC_SCL: R62.1 U8.23(SCL) U30.6(SCL)
IIC_SDA: R65.1 U8.24(SDA) U30.5(SDA)
KEY0: KEY0.2
KEY1: KEY1.2
KEY2: KEY2.2
LED0: D0.2(K)
LED1: D1.2(K)
LIGHT_SENSOR: R60.1
NRF_CE: U6.3(CE)
NRF_CS: U6.4(CSN)
NRF_IRQ: R37.1 U9.2(RE) U9.3(DE)  [also labelled RS485_RE]
REMOTE_IN: R63.1  [project net DCMI_XLCK]
RS485_RX: P9.5 U9.4(DI)
RS485_TX: P9.6 U9.1(RO)
SDIO_CMD: R39.1 SD_CARD.2(CMD)  [project net PD2]
SDIO_D2: R42.1 SD_CARD.9(DATA2)  [project net PC10]
SDIO_SCK: SD_CARD.5(CLK)  [project net PC12]
SPI1_MISO: U6.7(MISO) U11.2(SO)  [project net JTRST]
SPI1_MOSI: U6.6(MOSI) U11.5(SI)  [project net PB5]
SPI1_SCK: U6.5(SCK) U11.6(CLK)  [project net JTDO]
STM_ADC: P12.2  [project net PA5]
TPAD: P12.1 R64.1
U2_RX: P9.1 U5.11(DIN1)
U2_TX: P9.2 U5.12(ROUT1)
U3_232RX: COM3.4 U5.8(RIN2)
U3_232TX: COM3.3 U5.7(DOUT2)
U3_RX: P10.1 U5.10(DIN2)
U3_TX: P10.2 U5.9(ROUT2)
USART2_RX: P9.4  [project net PA3]
USART2_TX: P9.3  [project net ETH_MDIO]
USART3_RX: P10.4  [project net PB11]
USART3_TX: P10.3  [project net PB10]
USB_D+: P11.3  [project net PA12]
USB_D-: P11.4  [project net PA11]
USB_DM: R52.2 USB_HOST.2(D-) USB_SLAVE.2(D-)
USB_DP: R53.2 USB_HOST.3(D+) USB_SLAVE.3(D+)
USB_PWR: R57.1  [project net JTDI]
WK_UP: KEY_UP.2  [project net PA0]
NetBEEP_2: BEEP.2(G) Q1.3(C)
NetC64_1: C64.1 U5.1(C1+)
NetC64_2: C64.2 U5.3(C1-)
NetC66_2: C66.2 U5.2(V+)
NetC67_1: C67.1 U5.5(C2-)
NetC67_2: C67.2 U5.4(C2+)
NetC68_2: C68.2 U5.6(V-)
NetC73_2: C73.2 C74.2 R49.1 U8.8(VLOGIC) U8.13(VDD)
NetC76_2: C76.2 U8.20(CPOUT)
NetC77_2: C77.2 U8.10(REGOUT)
NetC80_2: C80.2 MOS1.3(D) USB_HOST.1(VCC)
NetCAN_1: CAN.1 R51.2 U10.7(CANH)
NetCAN_2: CAN.2 R51.1 U10.6(CANL)
NetCOM2_2: COM2.2 U5.14(DOUT1)
NetCOM2_3: COM2.3 U5.13(RIN1)
NetD0_1: D0.1(A) R41.1
NetD1_1: D1.1(A) R46.1
NetLS_2: LS.2 R58.1 R60.2
NetMOS1_1: MOS1.1(G) R54.2
NetP11_5: P11.5 R53.1
NetP11_6: P11.6 R52.1
NetPWR_1: PWR.1(A) R47.1
NetQ1_2: Q1.2(B) R59.2 R61.2
NetQ2_2: Q2.2(B) R57.2
NetQ2_3: Q2.3(C) R54.1 R56.1
NetR37_2: R37.2 U6.8(IRQ)
NetR38_2: R38.2 R44.1 RS485.2 U9.6(A)
NetR40_1: R40.1 R44.2 RS485.1 U9.7(B)
NetR45_2: R45.2 U8.12(INT)
NetR63_2: R63.2 R66.1 U13.1(DATA)

Not connected (* = marked no-connect by the designer): COM2 1 4 6 7 8 9; COM3 2 5 6 7 8 9; SD_CARD 10(CD) 11(GND) 12(WP); U8 2(NC) 3(NC) 4(NC) 5(NC) 6(AUX_DA) 7(AUX_CL) 14(NC) 15(NC) 16(NC) 17(NC) 19(RESV) 21(RESV) 22(RESV); U10 5(Vref); USB_SLAVE 4(NC)

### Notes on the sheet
- RS232
- GPS等
- NRF24L01
- OV2640
- MPU6050
- LED
- SD
- RS485
- KEY
- CAN&USB
- EEPROM
- 光敏传感器
- FLASH
- DHT11&DS18B20
- 红外接收
- ADC&DAC
- BEEP
- T_PAD

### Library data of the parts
C63-C82 = C
CAN RS485 = HEAD2
COM2 COM3 = DB9
D0 D1 PWR = LED2: Typical RED, GREEN, YELLOW, AMBER GaAs LED
KEY0-KEY2 KEY_UP = KEY_M
LS = LSENS: LIGHT SENS
MOS1 = MOS-P: IRLML6401/SI2301
P8 = Header 9X2: Header, 9-Pin, Dual row
P9-P11 = Header 3X2: Header, 3-Pin, Dual row
P12 = Header 4: Header, 4-Pin
Q1 Q2 = NPN: 8050/BCW846/BCW847
R37-R66 = R
TPAD = TPAD: ALIENTEK TPAD
U5 = MAX3232
U7 = ATK-HC05
U8 = MPU6050: 9轴运动处理传感器
U9 = MAX3485
U10 = SN65HVD230D
U11 = W25X16: W25X16;SST25VF016;MX25L1605
U12 = DHT11: 数字温湿度传感器
U30 = 24C256
USB_HOST = USB_A_90
USB_SLAVE = USB5

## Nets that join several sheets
GND: PCU1 (68 pins), CPU2 (60 pins), CPU3 (58 pins)
VCC3.3: PCU1 (15 pins), CPU2 (44 pins), CPU3 (38 pins)
VCC5: PCU1 (14 pins), CPU2 (C38.1 TFTLCD.28), CPU3 (6 pins)
VUSB: PCU1 (F1.2 USB_232.1), CPU3 (USB_SLAVE.1)
1WIRE_DQ: CPU2 (P4.14 U4.124), CPU3 (P8.18 R55.2 U12.2)
3D_INT: CPU2 (P3.19 U4.26), CPU3 (R45.1 U7.1)
BEEP: CPU2 (P3.18 U4.20), CPU3 (R59.1)
BOOT0: PCU1 (R73.2), CPU2 (R34.1 U4.138)
DCMI_D0: PCU1 (U2.11), CPU2 (P4.31 U4.96), CPU3 (P8.8)
DCMI_D1: CPU2 (P4.30 U4.97), CPU3 (P8.9)
DCMI_D2: CPU2 (P4.29 U4.98), CPU3 (P8.10 R50.1 SD_CARD.7)
DCMI_D3: CPU2 (P4.28 U4.99), CPU3 (P8.11 R43.1 SD_CARD.8)
DCMI_D4: CPU2 (P4.22 U4.112), CPU3 (P8.12 R48.1 SD_CARD.1)
DCMI_D5: CPU2 (P4.4 U4.136), CPU3 (P8.13)
DCMI_D6: CPU2 (P3.5 U4.4), CPU3 (P8.14)
DCMI_D7: CPU2 (P3.8 U4.5), CPU3 (P8.15)
DCMI_HREF: CPU2 (P3.25 U4.40), CPU3 (P8.5 P12.3)
DCMI_PCLK: CPU2 (P3.27 U4.42), CPU3 (P8.16)
DCMI_RESET: CPU2 (P4.8 U4.132), CPU3 (P8.7)
DCMI_SCL: CPU2 (P4.16 U4.122), CPU3 (P8.4)
DCMI_SDA: CPU2 (P4.15 U4.123), CPU3 (P8.6)
DCMI_VSYNC: CPU2 (P4.3 U4.137), CPU3 (P8.3)
DCMI_XLCK: CPU2 (P4.27 U4.100), CPU3 (R63.1)
ETH_MDC: PCU1 (U1.13), CPU2 (P3.22 U4.27)
ETH_MDIO: PCU1 (R2.1), CPU2 (U4.36), CPU3 (P9.3)
ETH_RESET: PCU1 (R10.2 U1.15), CPU2 (P4.19 U4.117)
F_CS: CPU2 (P4.43 U4.75), CPU3 (U11.1)
GBC_KEY: CPU2 (P3.16 U4.18), CPU3 (U7.2)
I2S_LRCK: PCU1 (U2.7), CPU2 (P3.44 U4.73)
I2S_SCLK: PCU1 (U2.8), CPU2 (P3.41 U4.74)
I2S_SDIN: PCU1 (U2.10), CPU2 (P3.24 U4.29)
I2S_SDOUT: PCU1 (U2.9), CPU2 (P3.21 U4.28)
IIC_SCL: PCU1 (U2.16), CPU2 (P4.2 U4.139), CPU3 (R62.1 U8.23 U30.6)
IIC_SDA: PCU1 (U2.17), CPU2 (P4.1 U4.140), CPU3 (R65.1 U8.24 U30.5)
JTDI: CPU2 (JTAG.5 P4.24 R29.2 U4.110), CPU3 (R57.1)
JTDO: CPU2 (JTAG.13 P4.7 R33.2 U4.133), CPU3 (U6.5 U11.6)
JTRST: CPU2 (JTAG.3 P4.6 R28.2 U4.134), CPU3 (U6.7 U11.2)
KEY0: CPU2 (P3.6 U4.3), CPU3 (KEY0.2)
KEY1: CPU2 (P3.3 U4.2), CPU3 (KEY1.2)
KEY2: CPU2 (P3.4 U4.1), CPU3 (KEY2.2)
LED0: CPU2 (P3.17 U4.21), CPU3 (D0.2)
LED1: CPU2 (P3.20 U4.22), CPU3 (D1.2)
LIGHT_SENSOR: CPU2 (P3.15 U4.19), CPU3 (R60.1)
NRF_CE: CPU2 (P4.34 U4.91), CPU3 (U6.3)
NRF_CS: CPU2 (P4.33 U4.92), CPU3 (U6.4)
NRF_IRQ: CPU2 (P4.32 U4.93), CPU3 (R37.1 U9.2 U9.3)
PA0: CPU2 (P3.26 U4.34), CPU3 (KEY_UP.2)
PA1: PCU1 (U1.14), CPU2 (P3.23 U4.35)
PA3: PCU1 (R20.1), CPU2 (U4.37), CPU3 (P9.4)
PA5: CPU2 (P3.28 U4.41), CPU3 (P12.2)
PA7: PCU1 (U1.11), CPU2 (P3.30 U4.43)
PA11: CPU2 (U4.103), CPU3 (P11.4)
PA12: CPU2 (U4.104), CPU3 (P11.3)
PB5: CPU2 (P4.5 U4.135), CPU3 (U6.6 U11.5)
PB10: CPU2 (U4.69), CPU3 (P10.3)
PB11: CPU2 (U4.70), CPU3 (P10.4)
PC4: PCU1 (U1.8), CPU2 (P3.29 U4.44)
PC5: PCU1 (U1.7), CPU2 (P3.32 U4.45)
PC10: CPU2 (P4.23 U4.111), CPU3 (R42.1 SD_CARD.9)
PC12: CPU2 (P4.21 U4.113), CPU3 (SD_CARD.5)
PD2: CPU2 (P4.20 U4.116), CPU3 (R39.1 SD_CARD.2)
PG11: PCU1 (U1.16), CPU2 (P4.12 U4.126)
PG13: PCU1 (U1.17), CPU2 (P4.10 U4.128)
PG14: PCU1 (U1.18), CPU2 (P4.9 U4.129)
RESET: PCU1 (D7.1), CPU2 (6 pins)
RXD: PCU1 (U17.3), CPU2 (P6.4)
TXD: PCU1 (U17.2), CPU2 (P6.2)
